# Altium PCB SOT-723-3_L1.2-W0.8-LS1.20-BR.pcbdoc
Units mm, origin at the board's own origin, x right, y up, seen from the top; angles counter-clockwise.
Board outline 14.55 x 14.31 mm, 2 copper layers (Top Layer, Bottom Layer), stack 0 mm thick; 1 components, 0 nets, 3 pads, 0 vias.
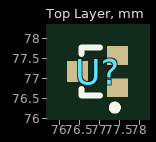
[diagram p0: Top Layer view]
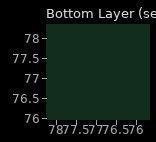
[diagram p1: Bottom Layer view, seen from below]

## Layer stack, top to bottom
Top Layer: signal copper (thickness not stored)
Bottom Layer: signal copper (thickness not stored)

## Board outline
84.4,69.85 69.85,69.85 69.85,84.16 84.4,84.16

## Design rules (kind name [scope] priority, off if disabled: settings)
PasteMaskExpansion "Paste Mask Expansion" [All] p1: expansion=0
SolderMaskExpansion "Solder Mask Expansion" [IsVia] p1: expansion=-25.4 istentingtop=TRUE
SolderMaskExpansion "Solder Mask Expansion" [All] p2: expansion=0.051 istentingtop=FALSE

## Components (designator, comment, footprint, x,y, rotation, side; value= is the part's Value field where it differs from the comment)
U? "" SOT-723-3_L1.2-W0.8-LS1.20-BR 76.96,77.175 r0 top

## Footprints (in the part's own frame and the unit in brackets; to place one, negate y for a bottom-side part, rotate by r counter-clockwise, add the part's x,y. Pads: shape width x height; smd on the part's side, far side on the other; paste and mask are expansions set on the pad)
SOT-723-3_L1.2-W0.8-LS1.20-BR [mil]
  rect 20.5x18.5 smd: 1(19.68,-15.75) 2(19.68,15.75)
  rect 20.5x20.5 smd: 3(-19.68,0)
  silkscreen extent -16,-38 20,24

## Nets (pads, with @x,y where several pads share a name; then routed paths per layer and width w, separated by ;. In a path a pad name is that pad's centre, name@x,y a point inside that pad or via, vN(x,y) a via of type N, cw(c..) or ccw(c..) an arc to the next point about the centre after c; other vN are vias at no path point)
pads on no net: U?.1 U?.2 U?.3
